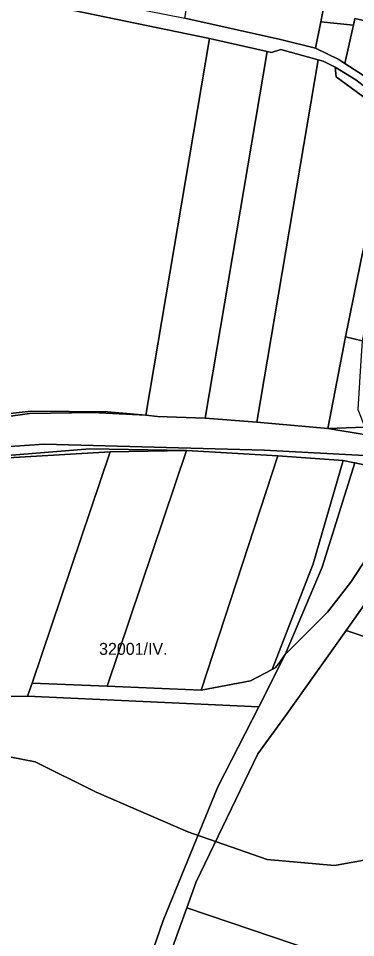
# Model space of a CAD drawing. Extents: x -545779 to -541342, y -1153413 to -1149956.
# Drawn here: x -544485.9 to -544345, y -1151642.9 to -1151258.7 of the extents above; entities that cross this region are included whole.
import ezdxf

# ---------------------------------------------------------------- set-up
doc = ezdxf.new("R2010")
doc.units = 0
for name, color, linetype in [('95560013', 7, 'Continuous'), ('95590013', 7, 'Continuous'), ('95600013', 7, 'Continuous'), ('95610013', 7, 'Continuous'), ('95640013', 7, 'Continuous'), ('95660013', 7, 'Continuous')]:
    doc.layers.add(name, color=color, linetype=linetype)

msp = doc.modelspace()

# ---------------------------------------------------------------- linework, layer by layer
at = {"layer": '95560013'}
for points in [[(-544534.87, -1151430.66), (-544560.82, -1151436.56), (-544598.93, -1151442.97), (-544581.26, -1151338.43), (-544563.58, -1151233.89), (-544518.88, -1151243.65), (-544406.01, -1151267.06), (-544432.64, -1151424.59), (-544448.69, -1151423.1), (-544480.64, -1151422.82), (-544509.45, -1151426.08)], [(-544427.72, -1151425.05), (-544432.64, -1151424.59), (-544406.01, -1151267.06), (-544381.96, -1151272.53), (-544407.86, -1151425.74)], [(-544407.86, -1151425.74), (-544381.96, -1151272.53), (-544380.12, -1151272.95), (-544376.21, -1151271.68), (-544360.6, -1151276), (-544386.22, -1151427.51)], [(-544358.51, -1151276.58), (-544353.61, -1151279.04), (-544353.12, -1151283.1), (-544338.53, -1151293.83), (-544336.38, -1151296.81), (-544334.45, -1151298.99), (-544333.93, -1151316.81), (-544337.5, -1151335.87), (-544342.65, -1151359.51), (-544347.81, -1151384.94), (-544349.21, -1151391.85), (-544356.61, -1151430.05), (-544386.22, -1151427.51), (-544360.6, -1151276)], [(-544332.09, -1151296.26), (-544328.86, -1151303.25), (-544328.78, -1151314.84), (-544329.71, -1151331.38), (-544329.9, -1151332.33), (-544340.23, -1151383.48), (-544342.25, -1151393.49), (-544349.21, -1151391.85), (-544347.81, -1151384.94), (-544342.65, -1151359.51), (-544337.5, -1151335.87), (-544333.93, -1151316.81), (-544334.45, -1151298.99), (-544336.38, -1151296.81), (-544338.53, -1151293.83), (-544353.12, -1151283.1), (-544353.61, -1151279.04), (-544344.97, -1151284.38), (-544336.96, -1151290.58)], [(-544572.23, -1151542.64), (-544540.71, -1151449.17), (-544506.92, -1151443.28), (-544447.61, -1151439.82), (-544480.22, -1151536.5), (-544482.08, -1151542.04), (-544556.71, -1151542.54)], [(-544480.22, -1151536.5), (-544447.61, -1151439.82), (-544415.66, -1151439.36), (-544448.86, -1151537.81)], [(-544409.57, -1151539.45), (-544377.46, -1151441.48), (-544350.17, -1151443.45), (-544362.73, -1151486.61), (-544379.85, -1151530.83), (-544388.93, -1151535.59)], [(-544330.23, -1151488.03), (-544267.95, -1151509.09), (-544275.88, -1151539.22), (-544348.98, -1151514.49)], [(-544411.63, -1151619.63), (-544385.88, -1151566.12), (-544374.27, -1151550.18), (-544348.98, -1151514.49), (-544275.88, -1151539.22), (-544308.61, -1151666.67), (-544415.57, -1151630.49)], [(-544455.29, -1151722.05), (-544457.82, -1151723.4), (-544605.38, -1151684.64), (-544556.71, -1151542.54), (-544482.08, -1151542.04), (-544385.47, -1151546.37), (-544402.51, -1151579.84), (-544425.47, -1151635.75)], [(-544319.09, -1151706.41), (-544325.87, -1151749.51), (-544330.86, -1151782.36), (-544337.64, -1151820.46), (-544340.91, -1151841.16), (-544342.22, -1151847.52), (-544474.71, -1151802.71), (-544442.81, -1151708.38), (-544438.68, -1151702.96), (-544432.02, -1151684.69), (-544431.97, -1151675.83), (-544415.57, -1151630.49), (-544308.61, -1151666.67), (-544309.29, -1151669.8)]]:
    msp.add_lwpolyline(points, close=True, dxfattribs=at)
at = {"layer": '95590013'}
for points in [[(-544358.05, -1151252.48), (-544358.15, -1151252.98), (-544359.55, -1151260.12), (-544361.72, -1151271.16), (-544376.33, -1151267.55), (-544416.31, -1151258.67), (-544392.55, -1151118.14), (-544340.12, -1151137.33), (-544340.13, -1151138.59), (-544349.7, -1151135.7), (-544355.92, -1151205.89), (-544357.7, -1151225.87), (-544353.73, -1151226.36), (-544354.93, -1151234.65), (-544355.95, -1151241.9)], [(-544336.85, -1151254.74), (-544326.33, -1151255.53), (-544324.7, -1151255.9), (-544326.16, -1151263.08), (-544330.01, -1151262.21), (-544341.03, -1151259.73), (-544345.32, -1151258.76), (-544345.94, -1151261.56), (-544359.55, -1151260.12), (-544358.15, -1151252.98), (-544358.05, -1151252.48)], [(-544349.44, -1151277.57), (-544352.01, -1151275.9), (-544361.72, -1151271.16), (-544359.55, -1151260.12), (-544345.94, -1151261.56), (-544346.17, -1151262.61)], [(-544331.29, -1151455.07), (-544323.85, -1151458.96), (-544346.93, -1151494.3), (-544356.79, -1151506.85), (-544374.44, -1151524.6), (-544358.92, -1151488.07), (-544345.38, -1151444.48), (-544328.51, -1151448.1)]]:
    msp.add_lwpolyline(points, close=True, dxfattribs=at)
at = {"layer": '95600013'}
msp.add_lwpolyline([(-544377.46, -1151441.48), (-544409.57, -1151539.45), (-544448.86, -1151537.81), (-544415.66, -1151439.36)], close=True, dxfattribs=at)
at = {"layer": '95610013'}
msp.add_lwpolyline([(-544349.21, -1151391.85), (-544342.25, -1151393.49), (-544342.89, -1151403.92), (-544344.02, -1151422.2), (-544341.1, -1151429.5), (-544356.61, -1151430.05)], close=True, dxfattribs=at)
at = {"layer": '95640013'}
for points in [[(-544517.96, -1151238.54), (-544416.31, -1151258.67), (-544376.33, -1151267.55), (-544361.72, -1151271.16), (-544352.01, -1151275.9), (-544349.44, -1151277.57), (-544339.82, -1151283.83), (-544335.78, -1151285.78), (-544332.89, -1151286.27), (-544330.54, -1151284.54), (-544332.09, -1151296.26), (-544336.96, -1151290.58), (-544344.97, -1151284.38), (-544353.61, -1151279.04), (-544358.51, -1151276.58), (-544360.6, -1151276), (-544376.21, -1151271.68), (-544380.12, -1151272.95), (-544381.96, -1151272.53), (-544406.01, -1151267.06), (-544518.88, -1151243.65)], [(-544707.14, -1151456.12), (-544647.37, -1151451.12), (-544638.67, -1151449.66), (-544598.93, -1151442.97), (-544560.82, -1151436.56), (-544534.87, -1151430.66), (-544509.45, -1151426.08), (-544480.64, -1151422.82), (-544448.69, -1151423.1), (-544432.64, -1151424.59), (-544454.9, -1151423.44), (-544481.23, -1151423.83), (-544522.9, -1151429.64), (-544581.14, -1151441.43), (-544627.05, -1151449.27), (-544653.47, -1151452.86), (-544707.54, -1151457.79)], [(-544522.9, -1151429.64), (-544481.23, -1151423.83), (-544454.9, -1151423.44), (-544432.64, -1151424.59), (-544427.72, -1151425.05), (-544407.86, -1151425.74), (-544386.22, -1151427.51), (-544356.61, -1151430.05), (-544324.56, -1151435.4)], [(-544735.88, -1151473.84), (-544680.32, -1151469.51), (-544652.11, -1151466.54), (-544624.55, -1151462.6), (-544577.97, -1151454.24), (-544519.82, -1151443.71), (-544456.12, -1151438.64), (-544415.66, -1151439.36), (-544447.61, -1151439.82), (-544506.92, -1151443.28), (-544540.71, -1151449.17), (-544593.95, -1151458.46), (-544640.54, -1151466.58), (-544646.97, -1151467.7), (-544663.43, -1151469.03), (-544733.67, -1151474.7)], [(-544328.51, -1151448.1), (-544345.38, -1151444.48), (-544346.19, -1151444.28), (-544350.17, -1151443.45), (-544377.46, -1151441.48), (-544415.66, -1151439.36), (-544456.12, -1151438.64), (-544519.82, -1151443.71)], [(-544455.29, -1151722.05), (-544425.47, -1151635.75), (-544402.51, -1151579.84), (-544385.47, -1151546.37), (-544374.44, -1151524.6), (-544356.79, -1151506.85), (-544346.93, -1151494.3), (-544323.85, -1151458.96), (-544318.6, -1151449.9), (-544302.52, -1151452.98), (-544315.45, -1151471.39), (-544321.64, -1151475.91), (-544330.23, -1151488.03), (-544348.98, -1151514.49), (-544374.27, -1151550.18), (-544385.88, -1151566.12), (-544411.63, -1151619.63), (-544415.57, -1151630.49), (-544431.97, -1151675.83)]]:
    msp.add_lwpolyline(points, dxfattribs=at)
for points in [[(-544332.89, -1151286.27), (-544335.78, -1151285.78), (-544339.82, -1151283.83), (-544349.44, -1151277.57), (-544346.17, -1151262.61), (-544345.94, -1151261.56), (-544345.32, -1151258.76), (-544341.03, -1151259.73), (-544330.01, -1151262.21), (-544326.16, -1151263.08), (-544330.54, -1151284.54)], [(-544341.1, -1151429.5), (-544323.5, -1151432.72), (-544324.56, -1151435.4), (-544356.61, -1151430.05)], [(-544374.44, -1151524.6), (-544377.03, -1151528.36), (-544378.59, -1151530.19), (-544379.85, -1151530.83), (-544362.73, -1151486.61), (-544350.17, -1151443.45), (-544346.19, -1151444.28), (-544345.38, -1151444.48), (-544358.92, -1151488.07)], [(-544377.03, -1151528.36), (-544374.44, -1151524.6), (-544385.47, -1151546.37), (-544482.08, -1151542.04), (-544480.22, -1151536.5), (-544448.86, -1151537.81), (-544409.57, -1151539.45), (-544388.93, -1151535.59), (-544379.85, -1151530.83), (-544378.59, -1151530.19)]]:
    msp.add_lwpolyline(points, close=True, dxfattribs=at)
at = {"layer": '95660013'}
for points in [[(-544327.072, -1151247.821), (-544336.004, -1151291.204), (-544325.796, -1151297.584), (-544325.796, -1151315.448), (-544315.588, -1151329.483), (-544304.105, -1151347.347), (-544293.897, -1151360.107), (-544288.794, -1151367.762), (-544288.794, -1151370.314), (-544286.241, -1151377.97), (-544287.518, -1151393.282), (-544292.621, -1151409.869), (-544295.173, -1151425.181), (-544295.173, -1151432.837), (-544288.794, -1151439.216), (-544278.585, -1151446.872), (-544265.825, -1151449.424), (-544259.445, -1151453.252), (-544253.066, -1151460.908), (-544296.449, -1151449.424), (-544333.452, -1151441.768), (-544383.215, -1151439.216), (-544475.085, -1151436.665), (-544512.088, -1151439.216)], [(-544512.088, -1151439.216), (-544475.085, -1151436.665), (-544383.215, -1151439.216), (-544333.452, -1151441.768), (-544296.449, -1151449.424), (-544253.066, -1151460.908), (-544261.998, -1151506.843), (-544283.689, -1151588.505), (-544301.553, -1151594.884), (-544323.245, -1151605.092), (-544339.831, -1151610.196), (-544353.868, -1151612.748), (-544381.939, -1151610.196), (-544415.114, -1151598.712), (-544453.393, -1151582.125), (-544478.912, -1151569.365), (-544518.467, -1151561.709)], [(-544518.467, -1151561.709), (-544478.912, -1151569.365), (-544453.393, -1151582.125), (-544415.114, -1151598.712), (-544381.939, -1151610.196), (-544353.868, -1151612.748), (-544339.831, -1151610.196), (-544323.245, -1151605.092), (-544301.553, -1151594.884), (-544283.689, -1151588.505), (-544292.621, -1151633.163), (-544301.51, -1151661.3)]]:
    msp.add_lwpolyline(points, dxfattribs=at)

# ---------------------------------------------------------------- texts
msp.add_text('32001/IV.', height=5, rotation=0, dxfattribs=at).set_placement((-544452.193, -1151524.706))

doc.saveas('drawing.dxf')
